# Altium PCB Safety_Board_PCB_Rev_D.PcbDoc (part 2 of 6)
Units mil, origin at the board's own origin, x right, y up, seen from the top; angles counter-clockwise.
Board outline 11000 x 4400 mil, 6 copper layers (L1-TOP, L2-Plane, L3-Signal, L4-Signal, L5-Plane, L6-BOT); 712 components, 540 nets, 2214 pads, 875 vias.
Unrouted connection lines stored in the file: 3.
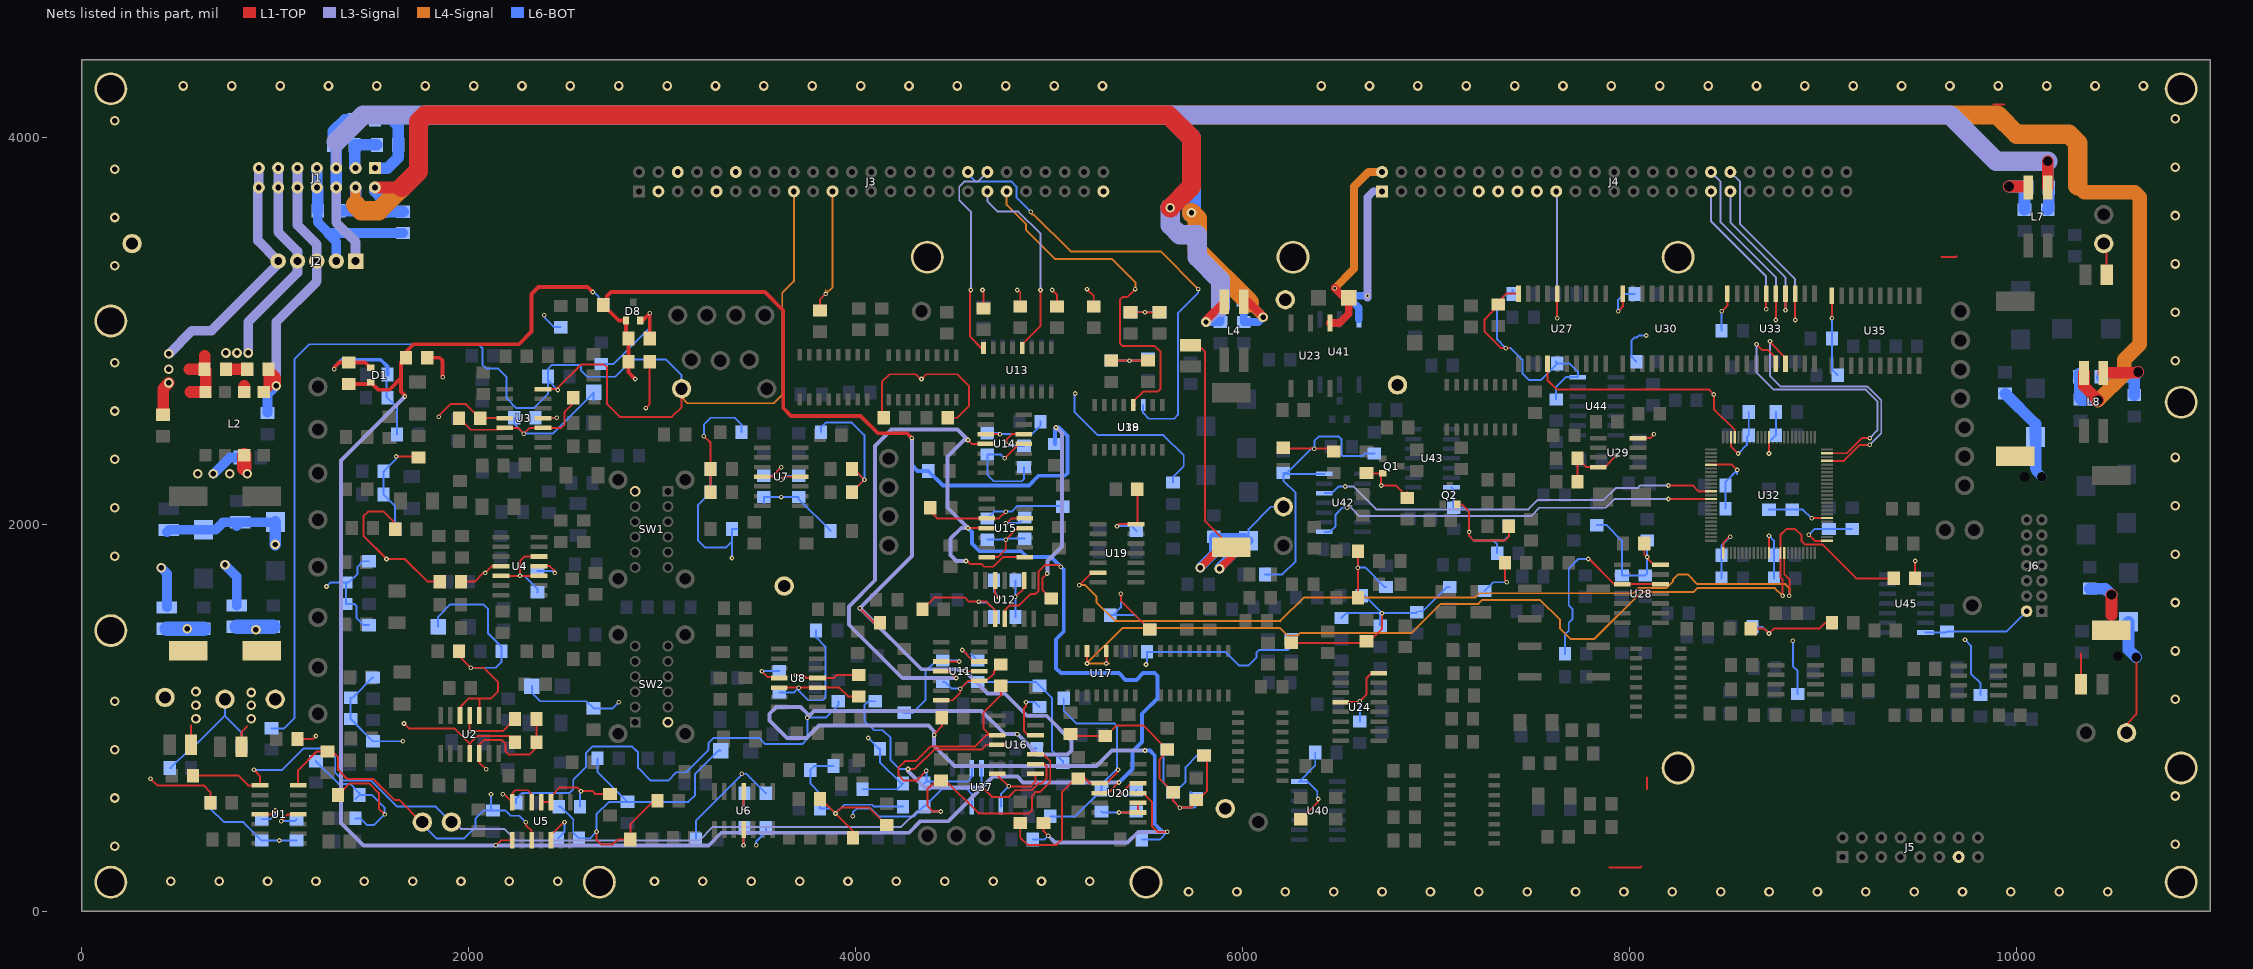
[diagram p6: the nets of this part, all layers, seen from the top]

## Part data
C1 C2 C3 C5 C18 C19 C25 C26 C27 C28 C29 C30 C31 C32 C34 C35 C40 C42 C47 C70 C78 C79 C80 C86 C88 C89 C90 C104 C105 C108 C109 C112 C114 C115 C117 C119 C121 C122 C124 C125 C126 C127 C129 C130 C131 C132 C133 C135 C136 C138 C139 C141 C144 C145 C148 C149 C150 C154 C158 C162: "Ceramic Chip Capacitor, 1uF, 50V, 10%, X7R"
C4 C6 C7 C9 C11 C22 C61 C62: "Ceramic Chip Capacitor, 0.022uF, 50V, 10%, X7R"
C8 C13 C66 C82: "Ceramic Chip Capacitor, 0.068uF, 50V, 10%, X7R"
C10 C12 C15 C16 C23 C24 C33 C36 C39 C41 C43 C51 C52 C53 C54 C55 C56 C57 C58 C59 C60 C67 C68 C71 C74 C75 C76 C77 C81 C83 C84 C85 C87 C91 C92 C93 C94 C95 C96 C97 C98 C99 C100 C101 C102 C103 C106 C107 C116 C118 C120 C123 C128 C134 C137 C140 C142 C143 C146 C147 C151 C152 C153 C155 C156 C160: "Ceramic Chip Capacitor, 0.1uF, 50V, 10%, X7R"
C14 C72: "Ceramic Chip Capacitor, 0.22uF, 50V, 10%, X7R"
C17 C21 C64 C73: "Ceramic Chip Capacitor, 2200pF, 50V, 5%, X7R"
C20 C63 C65 C69: "Ceramic Chip Capacitor, 0.33uF, 50V, 10%, X7R"
C37: "Ceramic Chip Capacitor, 0.01uF, 50V, 10%, X7R"
C38: "CAP TANTALUM, 10UF, 25V, 10%"
C44 C45 C48 C49: "Ceramic Chip Capacitor, 22uF, 25V, 20%, X5R"
C46 C50 C111 C113 C159 C161 C164 C165: "CAP TANTALUM, 100UF, 25V, 10%"
C110 C157 C163: "CAP TANTALUM 470UF 10V 10%"
D1 D8: "5V Shunt Voltage Reference, 1%"
D2 D3 D4 D5 D6 D7 D9 D13 D14 D15 D16 D17 D18 D20 D21 D23 D25 D27 D29 D30: "RECT FAST RECOVERY 200V 1A"
D10 D11 D12 D28: "TVS 400W 26V BIDIRECT SMA"
D19 D22 D24 D26: "TVS 400W 10V BIDIRECT SMA"
DS1 DS2 DS3 DS4 DS5 DS6 DS7: "LED, Green, Dome, 1210 SMD"
J1: "Header, 14-Pin, Dual row, Straight, Latch, Shroud"
J2: library part IRTF_STD_POWER, "Header, 5 position, single row, male, straight"
J3 J4: "Header, 50-Pin, Dual Row, Shrouded, Straight, Male, Shroud"
J5: "Header, 16-Pin, Dual row, Straight, Latch, Shroud"
J6: "Header, 14-Pin, Dual row, Straight, Shroud"
L1 L3: "Inductor, 5.6mH, 180mA, 15%"
L2: "Inductor, CM, 4 terminal, 500mA"
L4 L7 L8: "Inductor, CM, 1mH, 700mA, 50%"
L5 L6 L9: "Inductor, 1.2mH, 370mA, 15%"
Q1 Q2: "PNP Switching Transistor"
Q3: "NPN Switching Transistor"
R1 R3 R4 R8 R29 R49 R50 R54 R55 R63 R67 R68 R81 R114 R138 R139 R140 R141 R148 R149 R151 R153 R154 R155 R159 R160 R161 R172 R173 R177 R178 R179 R180 R183 R184 R186 R187 R189 R192 R194 R197 R198 R200 R201 R202 R203 R208 R210 R213 R227 R228 R235 R237 R238 R241 R255 R264 R275 R285 R292 R306 R307 R318 R319 R320 R321 R327 R329 R330 R331 R332 R333 R335 R343 R344 R363 R366 R369 R370 R373 R374 R375 R376 R377 R379 R380 R381 R383 R384 R385 R386 R388 R391: "Thick Film Chip Resistor, 0 Ohm, 1206 Size, 0.25 W"
R2 R6 R7 R26 R47 R51 R53 R56 R57 R58 R59 R60 R61 R64 R69 R76 R77 R85 R88 R90 R99 R106 R113 R117 R128 R129 R130 R132 R134 R135 R136 R142 R143 R146 R156 R158 R170 R171 R175 R176 R181 R182 R185 R196 R204 R205 R206 R209 R219 R239 R247 R248 R252 R266 R276 R279 R283 R287 R288 R295 R298 R308 R312 R316 R317 R322 R323 R324 R328 R337 R340 R341 R345 R354 R355 R358 R359 R361 R365 R371: "Thick Film Chip Resistor, 10k Ohm, 1% Tolerance, 1206 Size, 0.25 W"
R5 R35 R199 R231 R258 R263: "Thick Film Chip Resistor, 20k Ohm, 1% Tolerance, 1206 Size, 0.25 W"
R9 R10 R11 R12 R13 R14 R15 R16: "Thick Film Chip Resistor, 47.5k Ohm, 1% Tolerance, 1206 Size, 0.25 W"
R17 R23 R38 R46 R105 R110 R119 R120 R121 R122 R144 R150 R188 R191 R234 R259 R284 R296 R299 R304 R305 R311: "Thick Film Chip Resistor, 4.87k Ohm, 1% Tolerance, 1206 Size, 0.25 W"
R18 R24 R30 R33 R39 R48 R66 R70 R214 R216 R249 R262: "Thick Film Chip Resistor, 200k Ohm, 1% Tolerance, 1206 Size, 0.25 W"
R19 R20 R21 R41 R52 R220 R223 R224 R230 R232 R242 R256: "Thick Film Chip Resistor, 301k Ohm, 1% Tolerance, 1206 Size, 0.25 W"
R22 R42 R71 R229: "Thick Film Chip Resistor, 6.81k Ohm, 1% Tolerance, 1206 Size, 0.25 W"
R25 R34 R222 R245: "Thick Film Chip Resistor, 56.2k Ohm, 1% Tolerance, 1206 Size, 0.25 W"
R27 R74 R83 R86 R89 R94 R96 R97 R98 R103 R115 R169 R217 R265 R267 R270 R271 R278 R289: "Thick Film Chip Resistor, 100k Ohm, 1% Tolerance, 1206 Size, 0.25 W"
R28 R32 R40 R62 R82 R93 R95 R101 R108 R111 R112 R116 R118 R272 R274 R280 R286 R290 R291 R294 R297 R348 R349 R364 R378: "Thick Film Chip Resistor, 2k Ohm, 1% Tolerance, 1206 Size, 0.25 W"
R31 R233: "Thick Film Chip Resistor, 33.2k Ohm, 1% Tolerance, 1206 Size, 0.25 W"
R36 R43 R80 R109 R123 R124 R125 R126 R127 R131 R133 R137 R147 R157 R164 R174 R215 R250 R261 R300 R303 R309 R313 R314 R315 R325 R326 R338 R339 R342 R346 R347 R356 R357 R360 R362 R367 R368 R372: "Thick Film Chip Resistor, 100 Ohm, 1% Tolerance, 1206 Size, 0.25 W"
R37 R44 R211 R212 R218 R236 R240 R246: "Thick Film Chip Resistor, 68.1k Ohm, 1% Tolerance, 1206 Size, 0.25 W"
R45 R72 R251: "Thick Film Chip Resistor, 40.2k Ohm, 1% Tolerance, 1206 Size, 0.25 W"
R65 R73 R78 R193 R253 R260 R301 R334 R336 R387 R390: "Thick Film Chip Resistor, 1k Ohm, 1% Tolerance, 1206 Size, 0.25 W"
R75 R226: "Thick Film Chip Resistor, 182k Ohm, 1% Tolerance, 1206 Size, 0.25 W"
R79 R84 R87 R91 R92 R100 R102 R104 R107 R221 R225 R268 R269 R273 R277 R281 R282 R293: "Thick Film Chip Resistor, 1.21k Ohm, 1% Tolerance, 1206 Size, 0.25 W"
R145 R152 R310: "Thick Film Chip Resistor, 249 Ohm, 1% Tolerance, 1206 Size, 0.25 W"
R162 R163: "Thick Film Chip Resistor, 4.75k Ohm, 1% Tolerance, 1206 Size, 0.25 W"
R165 R166 R167 R168 R350 R351 R352 R353: "Thick Film Chip Resistor, 205 Ohm, 1% Tolerance, 1206 Size, 0.25 W"
R190 R195: "Thick Film Chip Resistor, 15.8 Ohm, 1% Tolerance, 1206 Size, 0.25 W"
R207: "Thick Film Chip Resistor, 12.7k Ohm, 1% Tolerance, 1206 Size, 0.25 W"
R243 R244 R254 R257: "Thick Film Chip Resistor, 15k Ohm, 1% Tolerance, 1206 Size, 0.25 W"
R302 R382 R389: "Thick Film Chip Resistor, 3.01 Ohm, 1% Tolerance, 1206 Size, 0.25W"
SW1 SW2: "Switch, Slide, 4PDT"
SW3 SW4: "Switch, Tactile, SPST, NO"
TP1 TP3 TP24 TP29 TP33 TP34 TP35 TP37 TP38 TP48 TP49 TP50: "Black, Compact Test Point, Thru Hole, Loop"
TP2 TP4 TP36 TP51 TP52: "Red, Compact Test Point, Thru Hole, Loop"
TP5 TP7 TP9 TP11: "Yellow, Compact Test Point, Thru Hole, Loop"
TP6 TP8 TP10 TP12: "Orange, Compact Test Point, Thru Hole, Loop"
TP13 TP14 TP15 TP16 TP17 TP18 TP19 TP20 TP21 TP22 TP23 TP25 TP26 TP27 TP28 TP30 TP31 TP32 TP39 TP40 TP41 TP42 TP43 TP44 TP45 TP46 TP47: "White, Compact Test Point, Thru Hole, Loop"
U1 U2 U3 U4 U6 U7 U8: "QUAD PRECISION OPAMP 14-SOIC"
U5 U11 U12 U14 U15 U16 U20 U37: "Quad Comparator"
U9 U10 U13 U17 U18 U21 U22 U25 U26 U31 U38 U39: "Photocoupler"
U19 U28 U40 U42 U43 U44 U45: "Hex Schmitt-Trigger Inverter"
U23 U41: "Solid State Relay, 2A, 80V"
U24: "IC LINE RCVR QUAD DIFF"
U27 U30 U33 U35: "Octal Bus Buffer with 3 State Outputs (Non Inverted)"
U29: "IC PRECISION TIMER , CMOS, 8-SOIC"
U32: "XC9500 CPLD with 72 Macrocells, 100-Pin TQFP, Commercial Grade"
U34 U36: "IC MPU SUPERVISORY CIRCUIT 8SOIC"

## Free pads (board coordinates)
  round 170 hole 141: ""(150,150) ""(150,1450) ""(150,3050) ""(150,4250) ""(2675,150) ""(4370,3380) ""(5500,150) ""(6260,3380) ""(8250,740) ""(8250,3380) ""(10850,150) ""(10850,740) ""(10850,2630) ""(10850,4250)

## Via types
v1: diameter 24, hole 12, L1-TOP to L6-BOT, 720 vias
v2: diameter 50, hole 28, L1-TOP to L6-BOT, 138 vias
v3: diameter 28, hole 50, L1-TOP to L6-BOT, 17 vias

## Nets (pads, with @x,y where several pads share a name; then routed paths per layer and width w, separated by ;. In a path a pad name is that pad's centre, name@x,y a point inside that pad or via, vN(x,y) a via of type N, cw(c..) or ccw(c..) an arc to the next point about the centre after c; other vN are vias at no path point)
15V_RTN: C1.2 C2.1 J1.11 J1.12 J2.4 L2.6 | length 1243.4
  L1-TOP w60: C1.2@745.12,2800 C2.1@854.88,2800 ; L2.6@840,2683.39 840,2715
  L3-Signal w50: v2(860,2885) 860,3045 1115,3300 1115,3410 1015,3510 J1.11@1015,3840
  other v2: 745,2885 802,2885
24V: D28.K J4.1 U41.6 | length 840.1
  L3-Signal w40: v1@6645,3170 6645,3690 6675,3720 J4.1@6720,3720
  L6-BOT w40: U41.6@6600,3059.29 6600,3118.5 D28.K@6548.5,3170 6558.5,3180 v1(6645,3180)
24VGND: J3.49 TP35.1
+5_VREF: C19.2 D8.1 R35.2 R46.1 R79.1 R92.1 R100.1 R102.1 R225.1 R258.2 R268.1 R275.1 R277.1 R282.1 R293.1 U11.11 U20.11 | length 15849.9
  L1-TOP w10: v1(4020,1565) 4095,1490 R79.1@4124.88,1490 ; v1(4405,910) 4405,915 4444.88,954.88 R92.1@4444.88,1000.12 ; v1(4565,1240) 4638.31,1240 U11.11@4638.43,1240.12 ; R100.1@4970,454.88 4970,415 v1(4995,390) ; v1(4990,1745) 4965,1720 4965,1660 5009.88,1615.12 R102.1@5010,1615.12 ; U20.11@5458.43,610 5485,610 5530,565 5530,440 5560,410 v1(5610,410)
  L1-TOP w20: R35.2@2694.76,3133.11 2775.12,3052.76 D8.1@2812.6,3052.76 2812.6,2972.28 C19.2@2824.88,2960 R46.1@2824.88,2840 2824.88,2785.12 v1(2860,2750) ; R35.2@2715,3165 2715,3180 2735,3200 3530,3200 3625,3105 3625,2600 3665,2560 4025,2560 4115,2470 4265,2470 v1(4290,2445)
  L3-Signal w15: 4522.19,1250 4528.65,1243.54 v1@4561.46,1243.54
  L3-Signal w20: v1(4290,2445) 4290,1835 v1(4020,1565) 4025,1565 4340,1250 4522.19,1250 ; v1@4561.46,1243.54 4680,1125 4770,1125 4885,1010 4985,1010 5115,880 5115,830 5095,810 4940,810 v1(4835,915) 4770,915 4650,1035 3785,1035 v1(3750,1000) 3750,1020 3715,1055 3590,1055 3555,1020 3555,985 3645,895 3745,895 3810,960 4375,960 4405,930 4405,855 4510,750 5245,750 5325,830 v1(5495,830) ; v1(4990,1745) 4990,1810 5065,1885 5065,2470 v1(5035,2500) ; v1(4995,390) 5030,355 5405,355 5460,410 v1(5610,410)
  L6-BOT w10: R225.1@2244.88,560 2244.88,579.88 2275,610 2520,610 2540,630 2540,680 2605,745 2605,815.96 2639.04,850 2845,850 2875,820 2875,740 2940,675 3030,675 3073,718 3123,718 3240,835 3240,870 3265,895 3500,895 3530,865 3725,865 3750,890 v1(3750,1000) 3845,1000 3910,1065 R258.2@3910,1084.88 ; v1(4835,915) 4910,840 R277.1@4935.12,840 ; R275.1@4915.12,370 4975,370 v1(4995,390) ; R293.1@5480.12,370 5570,370 v1(5610,410)
  L6-BOT w20: v1(4290,2445) 4290,2305 4320,2275 R268.1@4374.88,2275 4449.88,2200 4895,2200 4945,2250 5080,2250 5095,2265 5095,2455 5050,2500 v1(5035,2500) 5030,2495 R282.1@5030,2415.12 ; v1(5495,830) 5520,830 5545,805 5545,450 5585,410 v1(5610,410)
+5V_DIG: C33.2 C36.2 C39.2 C106.2 C116.2 C118.2 C120.2 C123.2 C128.2 C134.2 C137.2 C138.2 C139.2 C140.2 C142.2 C143.2 C145.2 C146.2 C147.2 C148.2 C149.2 C150.2 C151.2 C152.2 C154.2 C155.2 C156.2 C159.1 DS6.A J5.13 J6.2 L6.2 Q1.2 Q2.2 R77.2 R85.2 R113.2 R117.2 R129.2 R130.2 R132.2 R134.2 R135.2 R136.2 R142.1 R143.2 R146.2 R156.2 R158.2 R163.2 R170.2 R176.2 R181.2 R287.2 R288.2 R295.2 R298.2 R308.2 R312.2 R316.2 R317.2 R322.2 R323.2 R324.2 R328.2 R334.2 R336.2 R337.2 R340.2 R341.2 R345.2 R354.2 R355.2 R358.2 R359.2 R361.2 R365.2 R371.2 R382.2 TP51.1 U19.14 U24.4 U24.16 U27.20 U28.14 U29.4 U29.8 U30.20 U32.5 U32.26 U32.38 U32.51 U32.57 U32.88 U32.98 U33.20 U35.20 U40.14 U42.14 U43.14 U44.14 U45.14 | length 18332
  L1-TOP w10: R77.2@4144.88,2550 4144.88,2555.12 4135,2565 4135,2735 4175,2775 4310,2775 4335,2750 v1(4340,2750) 4365,2775 4525,2775 4585,2715 4585,2610 4525,2550 R85.2@4475.12,2550 ; v1(5350,1990) 5360,2000 U19.14@5448.43,2000 5455.12,2006.69 R113.2@5455.12,2180 R113.2@5448.43,2173.31 ; v1(5370,1640) 5370,1605 5520,1455 R117.2@5520,1454.88 ; R129.2@6210,2395.12 6215.12,2390 6455.12,2390 R134.2@6470,2375.12 ; R132.2@6250,1385.12 6630.24,1385.12 R143.2@6640,1394.88 6654.88,1394.88 6720,1460 v1(6720,1540) ; R130.2@6314.88,474.88 R130.2@6300,474.88 6390,564.88 v1(6390,580) ; U24.4@6506.57,1080 6600,1080 6640,1120 6640,1205 6665,1230 U24.16@6703.43,1230 ; R136.2@6595.12,1620 6595,1620.12 v1(6595,1775) 6595.12,1775.12 R135.2@6595.12,1860 ; R142.1@6640,2264.88 6642.28,2262.6 Q1.2@6722.76,2262.6 6715,2254.84 v1(6715,2200) 6790,2200 R146.2@6850,2140 ; R146.2@6850,2135.12 R146.2@6850,2165.35 ; Q2.2@7107.4,2102.76 7132.24,2102.76 7170,2065 7170,1940 7195,1915 7355,1915 7375.12,1935.12 R158.2@7375.12,1990 ; R156.2@7354.88,1800 7354.88,1710.12 v1(7365,1700) ; 7375,2910 7335,2910 7250,2995 7250,3060 7320,3130 7320,3150 7361.1,3191.1 U27.20@7425,3191.1 ; R163.2@7729.96,2340.04 7774.96,2295.04 7869.96,2295.04 v1(7929.96,2355.04) ; C36.2@7730.12,2220 R163.2@7730.12,2339.88 ; v1(7940,3100) 7965,3125 U30.20@7965,3191.1 ; U29.4@8042.32,2445.04 8105.04,2445.04 v1(8125,2465) ; C39.2@8075.12,1900 8075.12,1844.88 v1(8090,1830) 8090,1825 8125,1790 U28.14@8158.43,1790 ; U32.5@8420.79,2307.48 8527.52,2307.48 v1(8555,2280) ; v1(8475,3100) 8505,3130 U33.20@8505,3191.1 ; U32.26@8483.78,1850.79 8483.78,1903.78 8520,1940 v1(8520,1935) ; U32.98@8523.15,2449.21 8523.15,2401.85 v1(8560,2365) ; R170.2@8625.12,1460 8695,1460 v1(8720,1435) 8745,1460 8980,1460 9010,1490 R176.2@9044.88,1490 ; U32.38@8720,1850.79 v1@8720,1945 ; v1(8720,2365) U32.88@8720,2449.21 ; v1(8925,1945) 8956.22,1913.78 U32.51@9019.21,1913.78 ; v1(8940,2030) 8935,2030 8936.89,2031.89 U32.57@9019.21,2031.89 ; v1(9045,3065) U35.20@9045,3181.1 ; v1(9475,1810) 9475,1720.12 R181.2@9475.12,1720 R181.2@9480,1720 ; TP51.1@10450,3450 10465.12,3434.88 DS6.A@10465.12,3290
  L6-BOT w10: v1(5135,2675) 5130,2670 5130,2580 5250,2460 5590,2460 5695,2355 5695,2300 5640,2245 R298.2@5640,2215.12 ; R287.2@5315.12,1530 5444.88,1530 R295.2@5520,1454.88 ; R287.2@5330,1530 5370,1570 v1(5370,1640) ; v1(5350,1990) 5425.12,1990 C106.2@5450,1965.12 ; v1(5500,1275) 5500,1280 5505.12,1285.12 R288.2@5505.12,1340 5910,1340 5980,1270 6030,1270 6070,1310 6070,1335 6085,1350 6235,1350 6250,1365 R312.2@6250,1405.12 ; R308.2@6115.12,1740 6205,1740 6273,1808 6273,2162 6210,2225 C116.2@6210,2264.88 ; C118.2@6374.88,820 6374.88,753.31 U40.14@6291.57,670 6335,670 6385,620 6385,585 v1(6390,580) ; U42.14@6421.57,2260 6214.88,2260 C116.2@6210,2264.88 ; R317.2@6510,1515.12 6534.88,1540 6894.88,1540 R328.2@6900,1545.12 ; v1(6595,1775) 6635,1775 6735.12,1674.88 R323.2@6740,1674.88 ; C120.2@6605,980.12 v1(6605,1085) ; R316.2@6615.12,1630 6630,1630 v1(6720,1540) 6710,1530 R324.2@6710,1475.12 ; R322.2@6680,2364.88 6629.88,2364.88 6617.02,2352.02 6517.98,2352.02 6510,2360 6510,2440 6497,2453 6393,2453 6370,2430 v1(6370,2390) 6355,2390 6229.88,2264.88 C116.2@6210,2264.88 ; R328.2@6910,1550 6930,1550 7055.12,1675.12 R334.2@7070,1675.12 ; U43.14@7078.43,2190 7090,2178.43 C123.2@7090,2085.12 7144.88,2085.12 7170,2060 7170,1940 7195,1915 7350,1915 7375.12,1940.12 R340.2@7375.12,1990 ; R336.2@7250,1655.12 7294.88,1700 v1(7365,1700) ; 7295,1915 7314.88,1895.12 R341.2@7314.88,1850 ; R337.2@7394.88,3200 R337.2@7400,3200 ; R337.2@7394.88,3209.88 R337.2@7394.88,3190 7365,3190 7315,3140 7315,2955 v1(7360,2910) 7385,2910 7445,2850 7445,2780 7480,2745 7540.12,2745 C128.2@7625.12,2830 7690,2830 7731.57,2788.43 U44.14@7731.57,2760 7670,2760 7620,2710 R345.2@7620,2645.12 ; C128.2@7620,2835 C128.2@7620,2840 ; R354.2@7830,1994.88 7880.12,1994.88 7960,1915 R355.2@7960,1735.12 R361.2@8080,1735.12 8090,1745.12 R358.2@8090,1914.88 ; v1(7940,3100) 7940,3160 7970,3190 C134.2@8024.88,3190 ; R359.2@8034.88,2840 8010,2864.88 8010,2950 8025,2965 8037,2965 8047,2975 v1(8085,2975) ; C140.2@8474.88,1720 8474.88,1889.88 v1(8520,1935) ; C143.2@8474.88,3000 8475,3000.12 v1(8475,3100) ; C138.2@8495.12,2080 8495.12,2220.12 v1(8555,2280) 8555,2259.88 ; v1(8560,2365) 8605,2410 8605,2449.88 C137.2@8615.12,2460 C145.2@8615.12,2580 ; R365.2@8635.12,1470 8685,1470 v1(8720,1435) ; v1(8720,1940) 8744.88,1915.12 C151.2@8744.88,1720 ; C146.2@8720,2074.88 8895.12,2074.88 v1(8940,2030) ; v1(8720,2365) 8720,2425.12 C148.2@8754.88,2460 C147.2@8754.88,2580 ; v1(8925,1945) 8954.88,1974.88 C155.2@9150,1974.88 ; v1(9045,3065) 9045,2960.12 C152.2@9045.12,2960 9045.12,2800 R371.2@9075.12,2770 ; U45.14@9528.43,1440 9635.12,1440 C156.2@9640,1444.88 9946.14,1444.88 J6.2@10051.26,1550
  L6-BOT w50: 10097.96,2292.04 10097.96,2277.04 v3(10130,2245)
  L6-BOT w60: R382.2@9940,2674.88 10097.1,2517.78 10097.1,2451.8 C159.1@10097.96,2450.93 10097.96,2292.04
  other v1: 7170,1960
  other v3: 10040,2245
+5V_DIG_RAW: C158.2 J1.5 J1.6 J2.1 L7.1 R197.1 R202.2 R386.1 | length 10374
  L1-TOP w60: L7.1@10160,3740 v3(10160,3875)
  L3-Signal w50: J1.6@1315,3740 1315,3560 1415,3460 J2.1@1415,3360 ; J1.5@1315,3840 1315,3975
  L3-Signal w100: 1315,3975 1455,4115 9655,4115 9895,3875 v3(10160,3875)
  L6-BOT w60: J1.6@1315,3740 1315,3944.88 R197.1@1299.88,3960 1299.88,4029.88 1360,4090 R202.2@1404.88,4090 ; R386.1@10160,3625.12 10165.12,3630.24 C158.2@10165.12,3740 10160,3745.12 v3(10160,3875)
+5V_DIG_RTN: C158.1 J1.7 J1.8 J2.2 L7.2 R198.1 R213.2 R383.1 | length 1221.2
  L1-TOP w60: v3(9960,3745) L7.2@10050,3745
  L6-BOT w50: R198.1@1215,3624.88 R198.1@1219.88,3620 1219.88,3560.12 1275.12,3504.88 ; J2.2@1315,3360 1315,3460 1275.12,3499.88 1275.12,3504.88 ; R213.2@1660,3504.88 1275.12,3504.88
  L6-BOT w60: J1.7@1215,3840 J1.8@1215,3740 1219.88,3735.12 R198.1@1219.88,3620 ; v3(9960,3745) 10049.88,3745 C158.1@10054.88,3740 10040,3725.12 R383.1@10040,3625.12
+5V_SE: C111.1 DS3.A L5.2 R93.2 R95.2 R101.2 R108.2 R111.2 R112.2 R116.2 R118.2 R290.2 R291.2 R294.2 R297.2 R302.2 TP36.1 | length 3556.7
  L1-TOP w10: v1(4655,3210) 4655,3205 4660,3200 R93.2@4660,3115.12 ; v1(4835,3210) 4850,3195 R95.2@4850,3125.12 ; v1(5015,3210) 5040,3185 R101.2@5040,3125.12 ; v1(5195,3215) 5230,3180 R108.2@5230,3125.12 R108.2@5244.88,3125.12 ; R111.2@5320,2845.12 v1@5414.88,2845.12 ; v1@5415,2845.12 R116.2@5510,2845.12 ; R112.2@5420,3095.12 5494.88,3095.12 v1(5495,3095) 5569.88,3095 R118.2@5570,3095.12 ; DS3.A@5730,2925.12 5769.88,2925.12 5805,2890 5805,2015 L5.2@5940,1880 L5.2@5850,1880
  L1-TOP w40: v2(5780,1775) 5885,1880 L5.2@5940,1880 ; v2(5880,1770) 5945,1835 L5.2@5945,1885
  L6-BOT w10: R290.2@5320,2845.12 5414.88,2845.12 v1(5415,2845) ; v1@5415,2845.12 5500,2845.12 R294.2@5510,2855.12 ; R291.2@5420,3095.12 R297.2@5570,3095.12 ; v1@5494.88,3095.12 v1(5495,3095) ; R294.2@5509.88,2845 R294.2@5510,2845.12 ; C111.1@6030,1914.02 6030,1975 6145,2090 TP36.1@6210,2090
  L6-BOT w40: R302.2@5850,1934.88 6009.13,1934.88 C111.1@6030,1914.02
  L6-BOT w50: v2(5780,1775) 5850,1845 R302.2@5850,1934.88 ; v2(5880,1770) 5880,1775 6019.02,1914.02 C111.1@6030,1914.02
+5V_SE_RAW: C112.2 J1.1 L4.1 R202.1 R210.1 R307.1 | length 6078.9
  L1-TOP w40: L4.1@6005,3150 6030,3150 6110,3070 v2(6105,3070)
  L4-Signal w50: 6035,3145 6035,3140 v2(6105,3070)
  L4-Signal w100: v2(5735,3610) 5765,3580 5765,3415 6035,3145
  L6-BOT w40: C112.2@6000.12,3160 6005,3155.12 R307.1@6005,3045.12 6080.12,3045.12 v2(6105,3070)
  L6-BOT w50: R202.1@1515.12,4090 1750,4090
  L6-BOT w60: J1.1@1515,3840 1580,3840 1635.12,3895.12 1635.12,4059.88 1605,4090
  L6-BOT w100: 1750,4090 1775,4115 5615,4115 5735,3995 v2(5735,3610)
+5V_SE_RTN: C112.1 J1.2 L4.2 R203.1 R213.1 R306.1 | length 6356.1
  L1-TOP w40: v2(5810,3045) 5810,3055 L4.2@5905,3150
  L1-TOP w60: J1.2@1515,3740 1655,3740
  L1-TOP w100: 1655,3740 1740,3825 1740,4080 1775,4115 5615,4115 5735,3995 5735,3745 v2(5625,3635)
  L3-Signal w50: v2(5810,3045) 5885,3120
  L3-Signal w100: v2(5625,3635) 5625,3545 5675,3495 5765,3495 5765,3380 5885,3260 5885,3120
  L6-BOT w40: v2(5810,3045) 5810.12,3045.12 R306.1@5885,3045.12 5885,3155.12 C112.1@5889.88,3160
  L6-BOT w50: J1.2@1515,3740 J1.2@1520,3740 ; R213.1@1655.12,3620 R213.1@1660,3615.12
  L6-BOT w60: J1.2@1515,3740 1515,3720 1550.12,3684.88 R203.1@1550.12,3620 1555,3615.12 R213.1@1660,3615.12
+5V_WD: C165.1 DS7.A L9.2 R369.2 R380.2 R389.2 TP52.1 | length 1604.8
  L1-TOP w10: DS7.A@10332.85,1171.92 10332.85,1331.8 10332.96,1331.92 ; TP52.1@10567.97,921.92 10567.96,966.92 10617.96,1016.92 v3(10617.96,1311.92)
  L1-TOP w60: 10490,1530 v3(10490,1635)
  L6-BOT w10: v1(8842.96,1396.92) 8842.96,1266.92 8867.96,1241.92 R369.2@8867.96,1122.04 ; v1(9732.96,1401.92) 9762.96,1371.92 9762.96,1226.92 9812.96,1176.92 R380.2@9812.96,1117.04
  L6-BOT w60: R389.2@10377.96,1666.8 10458.2,1666.8 v3(10490,1635) ; C165.1@10577.96,1495.93 10577.96,1351.92 v3(10617.96,1311.92)
  other v3: 10522.96,1316.92
+5V_WD_RAW: C162.2 J1.3 L8.1 R197.2 R210.2 R391.1 | length 724.8
  L1-TOP w60: L8.1@10447.96,2781.92 10622.96,2781.92 v3(10627.96,2786.92)
  L6-BOT w50: R197.2@1410.12,3960 R197.2@1415,3955.12
  L6-BOT w60: J1.3@1415,3840 1410.12,3844.88 R197.2@1410.12,3960 R210.2@1524.88,3960 ; C162.2@10440,2760 10601.05,2760 v3(10627.96,2786.92) ; R391.1@10607.96,2667.04 10607.96,2766.92
+5V_WD_RTN: C162.1 J1.4 L8.2 R198.2 R203.2 R388.1 | length 11760.5
  L1-TOP w60: L8.2@10347.96,2781.92 10347.96,2712.04 v3(10420,2640)
  L4-Signal w50: 1415,3650 J1.4@1415,3740
  L4-Signal w75: 10315.5,3749.5 10350,3715 10610,3715 10635,3690 10635,2930 10555,2850 10555,2775 v3(10420,2640)
  L4-Signal w100: 1415,3650 1445,3620 1535,3620 1740,3825 1740,4080 1775,4115 9900,4115 10000,4015 10270,4015 10315.5,3969.5 10315.5,3749.5
  L6-BOT w60: R198.2@1330.12,3620 R203.2@1439.88,3620 1415,3644.88 J1.4@1415,3740 ; C162.1@10322.85,2777.85 C162.1@10322.85,2761.92 10325,2759.76 10325,2650 10335,2640 v3(10420,2640)
+15V: C10.2 C12.2 C16.2 C24.2 C49.2 C51.2 C74.2 C81.2 C84.2 C85.2 C93.2 C94.2 C96.2 C97.2 C98.2 C103.2 DS2.A L3.2 R46.2 R47.2 R88.2 R90.2 R99.2 R105.2 R106.2 R110.2 R119.2 R120.2 R121.2 R122.2 R195.2 R266.2 R276.2 R279.2 R283.2 R284.2 R296.2 R299.2 R304.2 R305.2 TP4.1 U1.4 U2.4 U3.4 U4.4 U5.3 U5.4 U6.4 U7.4 U8.4 U11.3 U12.3 U14.3 U15.3 U16.3 U20.3 U37.3 | length 11239
  L1-TOP w10: DS2.A@825.12,850 825.12,925.12 855,955 ; U1.4@921.57,500 980,500 v1(1000,520) ; v1(1665,970) 1690,945 1925,945 2004.65,865.35 ; v1(1845,2555) 1840,2555 1905,2620 1985,2620 2056.89,2548.11 U3.4@2186.22,2548.11 ; C10.2@1959.76,1703.11 2029.65,1703.11 2074.65,1748.11 v1(2084.65,1748.11) 2119.65,1783.11 U4.4@2166.22,1783.11 ; U2.4@2004.65,814.69 2004.65,865.35 ; 2206.89,873.11 C16.2@2239.53,873.11 ; C16.2@2239.53,903.23 C16.2@2239.53,873.11 ; U5.4@2375,563.43 U5.3@2425,563.43 2425,595 2470,640 2560,640 v1(2580,620) 2640,620 2654.88,605.12 R47.2@2730,605.12 ; v1(2915,2600) 2935.12,2620.12 R46.2@2935.12,2840 ; v1(3420,340) U6.4@3420,421.57 ; v1(3515,1240) 3545,1210 U8.4@3590,1210 ; U7.4@3516.57,2245 3565,2245 v1(3615,2295) ; R90.2@4344.88,1560 4404.88,1620 4565,1620 4585,1600 4675,1600 4720,1555 U12.3@4720,1511.57 ; v1(4365,725) 4315,675 4249.04,675 4220,704.04 4220,740 4255,775 4310,775 4387,852 4617,852 4675,910 U16.3@4731.57,910 ; R88.2@4384.88,2085 4384.88,2065.12 4420,2030 4740,2030 v1(4775,2065) ; U11.3@4441.57,1290.12 4534.88,1290.12 v1(4535,1290) ; U14.3@4671.57,2465 v1(4745,2465) ; U16.3@4695,910 4660,945 4660,1025 4750,1115 C24.2@4750,1164.88 ; R99.2@4850,454.88 4850,380 4888,342 5037,342 5065,370 5065,615 5134.88,684.88 5185.12,684.88 5210,660 5295,660 5355,720 v1(5355,730) ; R105.2@5110,914.88 5120,904.88 5294.88,904.88 5350,960 5484.88,960 R119.2@5610,834.88 5610,825 5570,785 5570,685.12 R120.2@5640.12,615 5640.12,569.88 v1(5675,535) 5735,535 5760,560 R121.2@5760,574.88 5769.88,574.88 5815,620 5815,789.88 R122.2@5800,804.88 ; R110.2@5290,890 R110.2@5290,904.88 ; 2004.65,865.35 2024.29,885 2025,885 2045,905 2207.64,905 C16.2@2239.53,873.11
  L6-BOT w10: C51.2@930,475.12 975.12,475.12 1000,500 v1(1000,520) ; C74.2@2575.12,540 2575.12,615.12 v1(2580,620) ; v1@3415,335 v1@3424.88,344.88 ; v1(3420,340) 3420,425.12 C84.2@3424.88,430 ; v1(3515,1240) 3515.12,1240.12 C85.2@3605,1240.12 ; C81.2@3525,2250.12 3570.12,2250.12 v1(3615,2295) ; R266.2@4250,1025 4294.88,1025 4360,1090.12 4360,1240.12 C94.2@4415.12,1295.24 ; C93.2@4355.12,660 4365,669.88 v1@4365,735 ; 4355.12,715.12 v1(4365,725) ; C93.2@4365.12,670 4575,670 4600,695 U37.3@4600,738.43 ; C94.2@4450,1295.24 4529.76,1295.24 v1(4535,1290) ; v1(4635,1600) 4640,1595 4680,1595 4714.88,1560.12 C96.2@4714.88,1520 ; C98.2@4680,2030.12 4714.88,2065 4805,2065 4835,2095 5064.88,2095 R283.2@5070,2089.88 ; C97.2@4680,2470.12 4739.88,2470.12 v1(4745,2465) 4910,2465 4955.12,2510.12 R276.2@4955.12,2530 ; R279.2@5005.12,490 5134.88,490 C103.2@5270,625.12 5270,655 5345,730 v1(5355,730) 5350,735 5350,955 5335,970 5140,970 5074.88,1035.12 R284.2@5074.88,1100 ; R299.2@5610,834.88 5610,825 5590,805 5590,664.88 R296.2@5640,614.88 5640,570 v1(5675,535) 5750,535 5760,545 R305.2@5760,584.88 R305.2@5730,614.88 ; R296.2@5649.88,614.88 5705,670 5705,745 5764.88,804.88 R304.2@5800,804.88
  L6-BOT w75: C49.2@800,1469.88 R195.2@990,1469.88
  other v2: 875,995 875,1065 875,1130 900,1455
+15V_RAW: C2.2 J1.9 J1.10 J2.3 L2.5 R194.1 | length 1640.5
  L1-TOP w50: L2.5@940,2683.39 965.12,2708.5 C2.2@965.12,2800 1005,2760.12 v2(1005,2715)
  L3-Signal w50: v2(1005,2715) 1005,3045 1215,3255 1215,3445 1115,3545 J1.9@1115,3840
  L6-BOT w50: R194.1@960,2575.12 960,2670 v2(1005,2715)
-5_VREF: C3.2 D1.2 R17.2 R231.1 R263.1 U5.8 U11.4 U12.4 U14.4 U15.4 U15.8 U16.4 U16.9 U20.4 U37.4 | length 17268.7
  L1-TOP w10: v1(2140,340) 2166.57,366.57 U5.8@2225,366.57 ; v1(4270,735) 4305,735 4405,835 4650,835 4675,860 U16.4@4731.57,860 ; U11.4@4441.57,1240.12 4484.88,1240.12 v1(4520,1205) ; v1(4570,1810) 4575,1810 4590,1795 4650,1795 4665,1780 4710,1780 4760,1830 U15.8@4873.43,1830 ; v1(4580,1980) U15.4@4676.57,1980 ; v1(4580,2435) 4600,2415 U14.4@4671.57,2415 ; v1(4655,640) 4705,590 4790,590 4825,625 4910.43,625 4945.43,660 4960,660 4985,685 4985,750 4975,760 U16.9@4928.43,760 U16.9@4928.43,751.57 ; U12.4@4770,1511.57 4770,1555 4795,1580 4845,1580 4905,1640 4930,1640 4945.48,1655.48 4945.48,1755.48 4980,1790 5050,1790 v1(5060,1780) ; U20.4@5270,610 5305,610 v1(5360,665)
  L1-TOP w20: C3.2@1380,2724.88 1485.04,2724.88 D1.2@1492.76,2732.6 1530,2695.35 1530,2695 1590,2695 1650,2755 ; v1(1670,2660) 1670,2665 1650,2685 1650,2835.12 R17.2@1674.88,2860 1674.88,2889.88 1715,2930 2260,2930 2325,2995 2325,3115 2325,3190 2360,3225 2435,3225 2615,3225 v1(2640,3200)
  L3-Signal w20: v1(1670,2660) 1340,2330 1340,455 1455,340 3240,340 3305,405 4275,405 4335,465 4480,465 4710,695 4835,695 4865,665 v1(5360,665) ; v1(4270,735) 4270,725 4355,640 v1(4655,640) ; v1(4520,1205) 4240,1205 3965,1480 3965,1575 4100,1710 4100,2405 4185,2490 4525,2490 v1(4580,2435) 4560,2435 4475,2350 4475,2085 v1(4580,1980) 4545,1980 4490,1925 4490,1840 4520,1810 v1(4570,1810)
  L6-BOT w10: v1(2640,3200) 2645,3200 2694.76,3150.24 R231.1@2694.76,3133.11 ; R263.1@4100,1084.88 4064.88,1084.88 4045,1065 4045,985 4095,935 4140,935 4180,895 4180,780 4225,735 v1(4270,735) ; U37.4@4650,738.43 4650,645 v1(4655,640)
  L6-BOT w20: v1(4580,1980) 4600,1960 4600,1900 4640,1860 4855,1860 4885,1830 5010,1830 5075,1765 5075,1445 5035,1405 5035,1255 5060,1230 5360,1230 5395,1195 5450,1195 5485,1230 5545,1230 5560,1215 5560,1100 5480,1020 5480,875 5430,825 5430,735 v1(5360,665)
-15V: C15.2 C23.2 C45.2 C52.2 C68.2 C71.2 C75.2 C83.2 C87.2 C91.2 C95.2 C99.2 C100.2 C101.2 C102.2 C107.2 DS1.K L1.2 R17.1 R190.2 TP2.1 U1.11 U2.11 U3.11 U4.11 U5.12 U6.11 U7.11 U8.11 U11.12 U12.12 U14.12 U15.12 U16.12 U20.12 U37.12 | length 4522.2
  L1-TOP w10: 565,960 565.12,959.88 DS1.K@565.12,860 ; v1(1030,465) 1065,500 U1.11@1118.43,500 ; U2.11@2004.65,1011.54 2004.65,930.35 v1(2005,930) 2176.42,930 C15.2@2239.53,993.11 C15.2@2229.65,993.11 ; U4.11@2363.07,1783.11 2419.65,1783.11 2444.65,1758.11 v1(2444.65,1748.11) ; U3.11@2383.07,2548.11 2384.96,2550 v1(2455,2550) ; U5.12@2425,366.57 2425,395 2490,460 v1(2495,460) ; v1(3420,535) U6.11@3420,618.43 ; v1(3615,2230) 3630,2245 U7.11@3713.43,2245 ; v1(3690,1220) 3730,1220 3745,1205 U8.11@3801.85,1205 3885,1205 3900.12,1220.12 C23.2@4015,1220.12 ; v1(4550,1350) 4609.88,1290.12 U11.12@4638.43,1290.12 ; U12.12@4720,1708.43 4720,1640 v1(4740,1620) ; v1(4775,2005) 4775,2000 4805,2030 U15.12@4873.43,2030 ; v1(4780,2410) 4780,2440 4805,2465 U14.12@4868.43,2465 ; v1(4880,1080) 4880,1060 4870,1050 4870,930 4890,910 U16.12@4928.43,910 ; v1(5365,600) 5425,660 U20.12@5458.43,660
  L1-TOP w20: R17.1@1785.12,2860 1850,2860 1865,2845 v1(1865,2760)
  L6-BOT w10: v1(1030,465) 1099.88,465 C52.2@1110,475.12 ; C68.2@2345.12,2550 v1(2455,2550) ; C71.2@2354.65,1758.23 2434.53,1758.23 v1(2444.65,1748.11) ; C75.2@2459.88,375 2495,410.12 v1(2495,460) ; v1(3420,535) 3420,605.12 C83.2@3424.88,610 ; v1(3615,2230) 3625,2230 3645.12,2250.12 C87.2@3705,2250.12 ; v1(3985,490) 3985,510 4005,530 4080,530 4121,489 4299,489 4350,540 C91.2@4355.12,540 4445.12,630 4575,630 4600,605 U37.12@4600,541.57 ; v1(4550,1350) 4604.76,1295.24 C99.2@4630,1295.24 4595.12,1330.12 ; C95.2@4714.88,1710 4714.88,1650.12 4740,1625 v1(4740,1620) ; v1(4775,2005) 4843.31,2005 C101.2@4873.43,2035.12 ; v1(4780,2410) 4784.88,2405.12 C100.2@4870,2405.12 ; v1(4880,1080) 4924.88,1080 C102.2@4950,1054.88 ; v1(5365,600) 5424.88,600 C107.2@5450,625.12
  L6-BOT w75: C45.2@440.12,1459.88 R190.2@630,1459.88
  other v2: 590,995 590,1065 590,1135 545,1459.88
-15V_RAW: C1.1 J1.13 J1.14 J2.5 L2.8 R1.1 | length 1822.4
  L1-TOP w60: R1.1@420,2565.12 420,2700 v2(450,2730) ; 555,2800 C1.1@634.88,2800 ; 561.61,2683.39 L2.8@640,2683.39 640,2794.88 C1.1@634.88,2800 ; 634.88,2869.88 C1.1@634.88,2800
  L3-Signal w50: v2(450,2880) 570,3000 670,3000 1015,3345 J2.5@1015,3360 910,3465 910,3735 J1.14@915,3740 J1.13@915,3840
  other v2: 450,2800
AGND: C3.1 C5.1 C6.1 C7.1 C10.1 C12.1 C15.1 C16.1 C19.1 C23.1 C24.1 C44.1 C45.1 C46.1 C47.1 C48.1 C49.1 C50.2 C51.1 C52.1 C53.1 C54.1 C55.1 C56.1 C57.1 C58.1 C59.1 C60.1 C61.1 C62.1 C67.1 C68.1 C71.1 C74.1 C75.1 C76.1 C77.1 C78.1 C79.1 C80.1 C81.1 C83.1 C84.1 C85.1 C86.1 C87.1 C88.1 C89.1 C90.1 C91.1 C92.1 C93.1 C94.1 C95.1 C96.1 C97.1 C98.1 C99.1 C100.1 C101.1 C102.1 C103.1 C107.1 D1.1 D8.2 D19.A D22.A D24.A D26.A J3.3 J3.6 J3.9 J3.12 J4.11 J4.13 J4.15 J4.17 L2.3 R3.1 R5.1 R23.1 R38.1 R45.1 R49.1 R54.1 R55.1 R63.1 R67.1 R68.1 R72.1 R81.1 R188.1 R189.1 R191.1 R193.1 R199.1 R200.1 R204.1 R205.2 R206.1 R208.1 R209.2 R227.1 R234.1 R237.1 R243.1 R244.1 R251.1 R254.1 R255.1 R257.1 R259.1 R285.1 SW1.7 SW2.7 TP3.1 TP24.1 TP33.1 TP38.1 U2.5 U2.10 U2.12 U3.5 U3.10 U4.5 U4.10 U4.12 U5.5 U5.7 U8.5 U8.10 U11.7 U11.10 U12.9 U14.11 U15.7 U15.11 U16.7 U16.8 U20.9 U20.10 U37.9 | length 25279.1
  L1-TOP w10: v1(355,685) 390,650 630,650 664.88,615.12 R3.1@664.88,560 ; R5.1@1115.12,890 1195,890 v1(1210,905) ; C5.1@1324.88,600 1384.88,660 1485,660 1535,610 1535,530 v1(1565,500) ; C7.1@1619.53,1973.11 1619.53,2005.47 1560,2065 1480,2065 1455,2040 1455,1940 v1(1575,1820) 1670,1820 1786.89,1703.11 C10.1@1849.53,1703.11 ; v1(1625,2350) 1734.88,2350 C6.1@1740,2344.88 ; C12.1@1949.53,2548.11 1949.65,2548.11 2009.65,2488.11 2176.22,2488.11 U3.5@2186.22,2498.11 2254.65,2498.11 v1(2284.65,2468.11) 2314.65,2498.11 2478.11,2498.11 2495,2515 2495,2580 2539.53,2624.53 R38.1@2539.53,2653.11 R38.1@2539.65,2653.11 ; R23.1@1949.76,1343.11 1949.76,1317.99 v1(2009.65,1258.11) 2076.89,1258.11 2150,1185 2150,1135 2115,1100 2000,1100 1954.65,1054.65 U2.12@1954.65,1011.54 ; U2.10@2054.65,1011.54 2054.65,1099.65 2055,1100 ; v1(2089.65,733.11) 2054.65,768.11 2054.65,859.65 2080,885 2170,885 2190,865 2190,825 2205,810 2315,810 2349.76,844.76 C15.1@2349.76,993.11 ; U4.5@2166.22,1733.11 v1(2264.65,1733.11) ; v1(2175,605) 2183.43,605 U5.7@2225,563.43 ; U5.7@2221.57,563.43 U5.7@2225,563.43 ; U5.5@2325,563.43 2325,605 2305,625 2240,625 2225,610 U5.7@2225,563.43 ; U4.10@2363.07,1733.11 v1(2264.65,1733.11) ; U4.12@2363.07,1833.11 2289.65,1833.11 2264.65,1808.11 v1(2264.65,1733.11) ; v1(2660,410) 2660,370 2685,345 2745,345 2770,370 R45.1@2834.88,370 2834.88,449.88 2955,570 R49.1@2974.88,570 ; v1(3215,2455) 3244.88,2425.12 3249.88,2425.12 R55.1@3249.88,2165 ; U8.5@3605,1155 3915,1155 3960.12,1109.88 C23.1@4015,1109.88 ; R63.1@3815.12,580 3820,580 3985.12,414.88 R72.1@3985.12,380 ; v1(3895,505) 3925,535 4070,535 4160,445 R81.1@4160,444.88 ; R68.1@3980.12,2165.12 v1(4045,2230) R67.1@4000,2275 ; U11.7@4441.57,1090.12 4500.12,1090.12 4540,1130 v1(4540,1150) 4580.12,1190.12 4675.12,1190.12 4715,1230 4715,1240.12 C24.1@4750,1275.12 ; U11.10@4633.31,1185 U11.10@4638.43,1190.12 ; U15.7@4676.57,1830 4735,1830 4775,1870 v1(4775,1920) 4835,1980 U15.11@4873.43,1980 ; U16.7@4731.57,710 4731.57,703.43 v1(4790,645) 4905,645 4928.43,668.43 U16.8@4928.43,710 ; v1(4770,2340) 4845,2415 U14.11@4868.43,2415 ; v1(4825,1625) 4870,1670 U12.9@4870,1708.43 ; v1(5360,510) U20.9@5458.43,510 U20.10@5458.43,560
  L1-TOP w20: v1(1305,2800) 1305,2810 1330.12,2835.12 1465.04,2835.12 D1.1@1492.76,2807.4 ; D8.2@2887.4,3052.76 2897.76,3052.76 v1(2935,3090) 2935.12,3089.88 C19.1@2935.12,2960
  L1-TOP w75: 840,2290 L2.3@840,2356.61
  L6-BOT w10: R189.1@454.88,740 460,740 565.12,845.12 R188.1@565.12,860 590,860 740,1010 ; C47.1@664.88,595.12 664.88,530.12 735,460 834.88,460 C51.1@930,364.88 C52.1@1110,364.88 ; TP3.1@740,1095 740,1010 ; R191.1@825.12,850 825.12,924.88 740,1010 ; R199.1@1210,775.12 1327.12,658 1387,658 1435.12,609.88 R208.1@1435.12,600 ; v1(1264.65,1678.11) 1284.53,1697.99 1377.99,1697.99 1425,1745 1425,1780 1453.23,1808.23 R206.1@1484.65,1808.23 ; C53.1@1364.65,1697.99 C56.1@1364.65,1588.23 1406.77,1588.23 1420,1575 1420,1515 1457.01,1477.99 C61.1@1484.65,1477.99 ; R200.1@1415.12,480 1440,480 1475,445 1510,445 v1(1565,500) 1565,535 1500,600 R208.1@1435.12,600 ; R208.1@1415.12,580 R208.1@1435.12,600 ; C62.1@1504.65,1208.23 1399.41,1102.99 C54.1@1389.65,1102.99 1389.65,993.11 1504.65,878.11 R209.2@1504.65,877.99 1659.53,877.99 v1(1659.65,878.11) ; C58.1@1564.65,2273.11 C58.1@1559.76,2273.11 ; C59.1@1574.65,2738.11 1574.65,2658.23 1629.53,2603.35 R204.1@1629.53,2463.11 ; R205.2@1619.53,1973.11 1619.53,2093.35 C55.1@1559.76,2153.11 C58.1@1559.76,2273.11 ; v1(1625,2350) 1625,2338.35 C58.1@1559.76,2273.11 ; D19.A@1841.5,1470 1841.5,1521.5 1905,1585 2075,1585 2100,1560 2100,1435 2169.76,1365.24 2169.76,1288.23 2139.65,1258.11 v1(2009.65,1258.11) ; C68.1@2234.88,2550 2234.88,2517.87 v1(2284.65,2468.11) 2433.11,2468.11 D24.A@2644.65,2679.65 ; v1(2264.65,1733.11) 2286.89,1733.11 2354.65,1665.35 C71.1@2354.65,1647.99 ; D22.A@2326.15,1163.11 2326.15,1128.85 2370,1085 2607.87,1085 R234.1@2644.65,1048.23 2743.23,1048.23 v1(2775,1080) ; v1(2390,3080) 2390,3070 2442.01,3017.99 R227.1@2474.65,3017.99 ; C74.1@2464.88,540 2475,540 2540,475 2540,405.12 C75.1@2570.12,375 2625,375 v1(2660,410) ; 2644.65,2639.65 D24.A@2644.65,2681.61 ; v1@2664.88,410 v1(2660,410) ; C77.1@2664.88,790 2664.88,720.24 R237.1@2820,565.12 ; C76.1@2684.65,2827.99 2747.99,2827.99 2935,3015 v1(2935,3090) ; C78.1@3174.88,370 3174.88,469.88 3410,705 v1(3410,710) 3435.12,710 C83.1@3535.12,610 C83.1@3535,610 ; v1(3215,2455) 3215,2515 3250,2550 3375,2550 3410.12,2514.88 R243.1@3410.12,2475 ; C79.1@3249.88,2285 C80.1@3249.88,2165 3185,2100.12 3185,1915 3220,1880 3330,1880 3360.12,1910.12 ; D26.A@3301.5,830 3290,830 3170,710 3170,600 3135.12,565.12 2725.12,565.12 2660,500 v1(2660,410) ; v1(3360,1825) 3360.12,1825.12 R244.1@3360.12,1975 R244.1@3390,1975 ; v1(3485,340) 3485,360 3535.12,410.12 C84.1@3535.12,430 ; C81.1@3525,2110 C81.1@3525,2139.88 ; C81.1@3525.12,2140 C81.1@3525,2139.88 ; C85.1@3605,1129.88 3679.88,1129.88 v1(3705,1155) 3705,1140 3755,1090 3830,1090 3843,1103 3843,1367 3794.88,1415.12 R255.1@3794.88,1450 ; R254.1@3819.88,2475 3819.88,2499.88 3845,2525 3980,2525 4045,2460 v1(4045,2230) ; R257.1@3869.88,1965 3705,2129.88 C87.1@3705,2139.88 3704.88,2140 v1(3615,2140) 3614.88,2139.88 C81.1@3525,2139.88 ; R259.1@3884.88,750 3785.12,750 R251.1@3765.12,730 3765.12,659.88 3815.12,609.88 C86.1@3815.12,530 3870,530 v1(3895,505) 3940,550 4084.04,550 4094.04,540 C91.1@4244.88,540 ; C89.1@3980.12,2165 3980.12,2165.12 v1(4045,2230) ; C88.1@3980.12,2285 3990,2285 v1(4045,2230) ; C90.1@4035.12,630 4214.88,630 C93.1@4244.88,660 4235,660 4124.88,770.12 C92.1@4124.88,840 4120,840 v1(4065,895) ; C94.1@4450,1185 4460,1185 4495,1150 v1(4540,1150) 4575,1185 C99.1@4630,1185 ; C99.1@4633.31,1185 4930.12,1185 5015,1100.12 5015,830 5070,775 R285.1@5070,765.12 ; C98.1@4680,1919.88 4774.88,1919.88 4779.88,1924.88 C101.1@4873.43,1924.88 ; U37.9@4750,541.57 4750,605 v1(4790,645) ; v1@4770,2335 v1(4770,2340) 4750.12,2359.88 C97.1@4680,2359.88 4680,2255 4713,2222 4857,2222 4870,2235 C100.1@4870,2294.88 ; C96.1@4825.12,1520 4825.12,1624.88 v1(4825,1625) 4825.12,1625.12 C95.1@4825.12,1710 ; C103.1@5270,514.88 5274.88,510 5445.12,510 C107.1@5450,514.88
  L6-BOT w20: v1(1305,2800) 1305,2810 1345,2850 1545,2850 1579.76,2815.24 C59.1@1579.76,2773.11
  L6-BOT w50: v2(410,1775) 440,1745 C45.1@440,1570.12 ; C44.1@440,1959.88 451.1,1970.98 690.98,1970.98 729.88,2009.88 998.9,2009.88 C50.2@1000,2010.98 ; v2(680,2260) 765,2345 R193.1@814.88,2345 ; v2(740,1790) 800,1730 C49.1@800,1580.12 ; C48.1@800,1989.88 C48.1@820,2009.88
  L6-BOT w60: v2(1000,1895) C50.2@1000,2010.98
  other v1: 1019.88,364.88
  other v2: 600,2260 765,2260 855,2260
BDEC: R2.2 R91.1 TP14.1 U1.1 U16.10 | length 5561.3
  L1-TOP w10: R2.2@575.12,700 810,700 860,650 U1.1@921.57,650 921.57,698.43 v1(890,730) ; v1(4440,515) 4400,515 4370,545 4370,630 4414.88,674.88 4465.12,674.88 4635,505 4895,505 4910,520 4910,595 4930,615 4950,615 5005,670 5005,775 4970,810 U16.10@4928.43,810
  L3-Signal w10: TP14.1@1910,460 1925,460 1960,425 2183.34,425 2243.34,365 3190,365 3260,435 4235,435 4315,515 v1(4440,515)
  L6-BOT w10: v1(890,730) 1035,730 1145,840 1265,840 1310,795 1310,715 1350,675 1495,675 1630,540 1830,540 TP14.1@1910,460
BHA: R6.2 R221.1 TP13.1 U1.14 U5.10 | length 1826.7
  L1-TOP w10: U1.14@1118.43,650 1118.43,728.43 1215.12,825.12 1294.88,825.12 1325,795 1325,730 1372,683 1507,683 1615,575 1640,575 1755,460 TP13.1@1760,460 ; v1(2295,460) 2295,445 2325,415 U5.10@2325,366.57
  L6-BOT w10: TP13.1@1760,460 1760,450 1835,375 1975,375 2035,435 2035,480 2075.12,520.12 2189.88,520.12 2216.77,493.23 2261.77,493.23 v1(2295,460) ; v1@2115,600 2115,530.12 R221.1@2125,520.12
  other v1: 2115,605
"BRAKE EN IN": J3.21 R65.1 | length 666.8
  L1-TOP w10: R65.1@3815,3105.12 3815,3160 v1(3845,3190) v1@3850,3190
  L4-Signal w10: 3845,3210 v1(3845,3190) 3880,3225 J3.21@3880,3720
"BRAKE ENABLE RELAY": D10.A J4.2 U23.4 | length 1053.6
  L1-TOP w40: U23.4@6450,3039.29 6499.29,3039.29 6548.5,3088.5 D10.A@6548.5,3170 ; v1(6475,3220) 6525,3170 D10.A@6565,3170
  L4-Signal w40: v1(6475,3220) 6575,3320 6575,3745 6650,3820 J4.2@6720,3820
BRAKE_RELEASE_IN_BUF: U19.6 U32.42 | length 4293.6
  L1-TOP w10: v1(5155,1685) 5220,1750 U19.6@5251.57,1750 ; U32.42@8798.74,1850.79 8798.74,1741.26 8825,1715 v1(8825,1630)
  L4-Signal w10: v1(5155,1685) 5185,1685 5245,1625 5245,1595 5340,1500 6195,1500 6317,1622 7202,1622 7223,1643 8018,1643 8045,1670 8190,1670 8224.15,1704.15 8224.15,1714.15 8250,1740 8300,1740 8350,1690 8805,1690 8825,1670 v1(8825,1630)
CHASSIS: pad. TP1.1 | length 364.1
  L1-TOP w10: 7895,225 8055,225 8060,230 ; 8090,630 8090,690 ; 9610,3380 9685,3380 9690,3385 ; 9880,4170 9935,4170
  other v2: 5720,100 5970,100 6220,100 6470,100 6720,100 6970,100 7220,100 7470,100 7720,100 7970,100 8220,100 8470,100 8720,100 8970,100 9220,100 9470,100 9720,100 9970,100 10220,100 10470,100 460,155 710,155 960,155 1210,155 1460,155 1710,155 1960,155 2210,155 2460,155 2960,155 3210,155 3460,155 3710,155 3960,155 4210,155 4460,155 4710,155 4960,155 5210,155 170,335 10820,345 170,585 10820,595 170,835 170,1085 10820,1095 10820,1345 10820,1595 170,1835 10820,1845 170,2085 10820,2095 170,2335 10820,2345 170,2585 170,2835 10820,2845 170,3085 10820,3095 170,3335 10820,3345 170,3585 10820,3595 170,3835 10820,3845 170,4085 10820,4095 525,4265 775,4265 1025,4265 1275,4265 1525,4265 1775,4265 2025,4265 2275,4265 2525,4265 2775,4265 3025,4265 3275,4265 3525,4265 3775,4265 4025,4265 4275,4265 4525,4265 4775,4265 5025,4265 5275,4265 6405,4265 6655,4265 6905,4265 7155,4265 7405,4265 7655,4265 7905,4265 8155,4265 8405,4265 8655,4265 8905,4265 9155,4265 9405,4265 9655,4265 9905,4265 10155,4265 10405,4265 10655,4265
CPLD_CLK: R348.1 U28.3 U28.12 | length 1017.9
  L1-TOP w10: v1(7785,1820) 7790,1820 7920,1690 U28.12@8158.43,1690
  L4-Signal w10: v1(7785,1820) v1@7790,1820
  L6-BOT w10: R348.1@7664.88,1330 7664.88,1429.88 7685,1450 7685,1490 7705,1510 7705,1560 7685,1580 7685,1770 7735,1820 v1(7785,1820)
"DEC EMERG N": J3.38 U13.8 | length 1072.8
  L1-TOP w10: v1(4595,3210) 4595,3205 4590,3200 4590,2970 4649.84,2910.16 U13.8@4660,2910.16
  L3-Signal w10: v1(4595,3210) 4595,3615 4535,3675 4535,3745 4560,3770 4630,3770 J3.38@4680,3820
"DEC EMERG N LATCH": J4.37 U33.14 | length 819.2
  L1-TOP w10: v1(8805,3105) U33.14@8805,3191.1
  L3-Signal w10: J4.37@8520,3720 8520,3560 8805,3275 v1(8805,3105)
"DEC EMERG S": J3.39 U18.4 | length 1896.6
  L1-TOP w10: v1(5445,3215) 5405,3175 5380,3175 5365,3160 5365,2935 5380,2920 5545,2920 5575,2890 5575,2700 5560,2685 5485,2685 5435,2635 U18.4@5435,2615.16 U18.4@5445.16,2615.16
  L4-Signal w10: J3.39@4780,3720 4780,3650 4880,3550 4880,3520 5030,3370 5325,3370 5445,3250 v1(5445,3215)
"DEC EMERG S LATCH": J4.38 U33.13 | length 1039.9
  L1-TOP w10: v1(8855,3055) U33.13@8855,3191.1
  L3-Signal w10: J4.38@8520,3820 8570,3770 8570,3550 8855,3265 v1(8855,3055)
"DEC OS LATCH": J4.19 U27.16 | length 783.2
  L1-TOP w10: v1(7625,3065) U27.16@7625,3191.1
  L3-Signal w10: J4.19@7620,3720 7625,3715 v1(7625,3065)
"DEC STOP N": J3.36 U39.6 | length 2401.8
  L4-Signal w10: 4910,3600 4920,3600 5110,3410 5575,3410 v1(5770,3215)
  L6-BOT w10: J3.36@4580,3820 4580,3810 4620,3770 4805,3770 4830,3745 4830,3690 v1(4905,3615) ; U39.6@5485,2615.16 5485,2575 5515,2545 5645,2545 5665,2565 5665,3090 5770,3195 v1(5770,3215)
"DEC STOP N LATCH": J4.35 U33.16 | length 809.2
  L1-TOP w10: v1(8705,3110) U33.16@8705,3191.1
  L3-Signal w10: J4.35@8420,3720 8420,3565 8705,3280 v1(8705,3110)
"DEC STOP S": J3.37 U13.4 | length 1024.6
  L1-TOP w10: U13.4@4860,2910.16 4860,2930 4955,3025 v1(4955,3210)
  L3-Signal w10: J3.37@4680,3720 4680,3670 4735,3615 4840,3615 4955,3500 v1(4955,3210)
"DEC STOP S LATCH": J4.36 U33.15 | length 1039.9
  L1-TOP w10: v1(8755,3055) U33.15@8755,3191.1
  L3-Signal w10: J4.36@8420,3820 8470,3770 8470,3560 8755,3275 v1(8755,3055)
"DEC VEL FEEDBACK": J3.17 R196.1 R226.2 TP16.1 U3.14 | length 7476.6
  L1-TOP w10: U3.14@2383.07,2698.11 v1@2454.65,2698.11 ; v1(2459.65,2693.11) 2459.65,2704.65 2580,2825 2700,2825 2715,2810 2715,2620 2780,2555 3050,2555 3100,2605 TP16.1@3100,2700
  L4-Signal w10: TP16.1@3100,2700 3100,2655 3130,2625 3575,2625 3620,2670 3620,3195 3680,3255 J3.17@3680,3720
  L6-BOT w10: R196.1@980,945.12 1045.12,945.12 1100,1000 1100,2855 1175,2930 2050,2930 2070,2910 2070,2825 2090,2805 2150,2805 2195,2760 2195,2650 2245,2600 2335,2600 2409.53,2674.53 2409.53,2802.99 2429.65,2823.11 2569.65,2823.11 2579.65,2813.11 2579.65,2795.35 2613,2762 2757,2762 2845,2850 3020,2850 3100,2770 TP16.1@3100,2700 ; R226.2@2409.53,2743.23 v1(2459.65,2693.11)
DEC_EMERG_N_LATCH: U32.74 U33.6 | length 1452.1
  L1-TOP w10: v1(8655,2930) 8685,2900 8715,2900 8755,2860 U33.6@8755,2828.9 ; U32.74@9019.21,2366.54 9121.54,2366.54 9200,2445 v1(9240,2445)
  L3-Signal w10: v1(8655,2930) 8655,2785 8745,2695 9220,2695 9280,2635 9280,2485 v1(9240,2445)
DEC_EMERG_NORTH_BUF_N: U32.14 U42.8 | length 2140.5
  L1-TOP w10: v1(8200,2130) 8420.47,2130 U32.14@8420.79,2130.32
  L3-Signal w10: v1(6540,2085) 6560,2085 6603,2042 7489.88,2042 7532.88,2085 7875,2085 7920,2130 v1(8200,2130)
  L6-BOT w10: U42.8@6421.57,1960 6450,1960 6480,1990 6480,2050 6515,2085 v1(6540,2085)
DEC_EMERG_S_LATCH: U32.72 U33.7 | length 1466
  L1-TOP w10: v1(8725,2945) 8725,2940 8805,2860 U33.7@8805,2828.9 ; U32.72@9019.21,2327.17 9107.17,2327.17 9190,2410 v1(9240,2410)
  L3-Signal w10: v1(8725,2945) 8725,2765 8778,2712 9228,2712 9300,2640 9300,2470 v1(9240,2410)
DEC_EMERG_SOUTH_BUF_N: U32.12 U42.12 | length 2126.9
  L1-TOP w10: v1(8200,2200) 8325,2200 8355.31,2169.69 U32.12@8420.79,2169.69
  L3-Signal w10: v1(6530,2195) 6570,2195 6689,2076 7475.79,2076 7524.79,2125 7865,2125 7927,2187 8042,2187 8055,2200 v1(8200,2200)
  L6-BOT w10: U42.12@6421.57,2160 6460,2160 6495,2195 v1(6530,2195)
DEC_LAB_SELECT: R181.1 U17.12 U17.14 U32.41 | length 5284
  L1-TOP w10: v1(5195,1280) U17.14@5195,1345.16 ; v1(5295,1280) U17.12@5295,1345.16 ; v1(8790,1630) 8790,1715 8779.06,1725.94 8779.06,1944.06 8810,1975 8855,1975 8888.13,1941.87 8888.13,1911.87 8905,1895 8995,1895 9170,1720 R181.1@9364.88,1720
  L4-Signal w10: 5310,1280 v1(5195,1280) 5378,1463 6192.96,1463 6230.96,1425 6285,1425 6298,1438 6873,1438 7023,1588 7218,1588 7239,1609 7536,1609 7640,1505 7640,1460 7693,1407 7817.96,1407 8060.96,1650 8330,1650 8350,1670 8750,1670 v1(8790,1630)
DEC_OVERSPEED_LATCH: U27.4 U32.97 | length 1240.4
  L1-TOP w10: U27.4@7575,2828.9 7575,2745 7625,2695 8410,2695 v1(8435,2670) 8435,2595 8542.83,2487.17 U32.97@8542.83,2449.21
